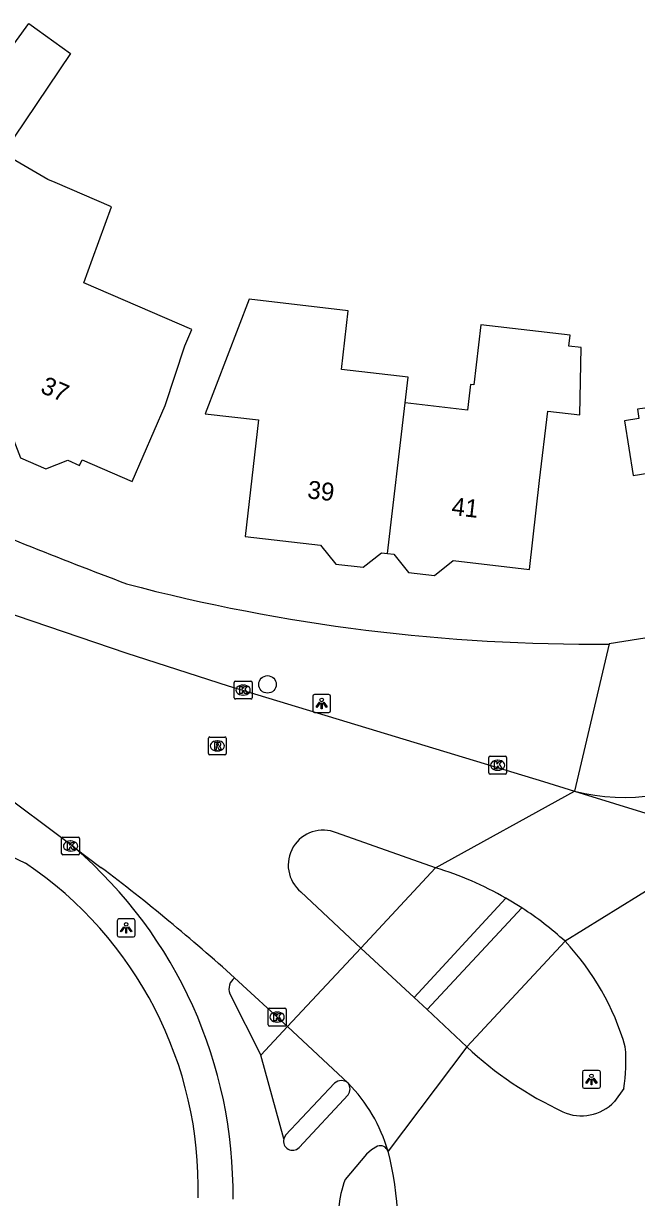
# Model space of a CAD drawing. Extents: x 161354 to 161876, y 382161 to 382804.
# Drawn here: x 161714.8 to 161749.1, y 382269.2 to 382334.8 of the extents above; entities that cross this region are included whole.
import ezdxf

# ---------------------------------------------------------------- set-up
doc = ezdxf.new("R2010")
doc.units = 0
for name, color, linetype in [('IMGEO_Boom', 7, 'Continuous'), ('IMGEO_Fietspad_open', 7, 'Continuous'), ('IMGEO_Kolk', 7, 'Continuous'), ('IMGEO_Lichtpunt', 7, 'Continuous'), ('IMGEO_Pand', 7, 'Continuous'), ('IMGEO_Pand_nummerreeks', 7, 'Continuous'), ('IMGEO_Rijbaan_lokaal_gesloten', 7, 'Continuous'), ('IMGEO_Rioolput', 7, 'Continuous'), ('IMGEO_Voetpad_open', 7, 'Continuous')]:
    doc.layers.add(name, color=color, linetype=linetype)

msp = doc.modelspace()

# ---------------------------------------------------------------- linework, layer by layer
at = {"layer": 'IMGEO_Boom'}
msp.add_circle((161728.459, 382297.901), 0.489, dxfattribs=at)
at = {"layer": 'IMGEO_Fietspad_open'}
for points in [[(161737.377, 382279.736), (161742.662, 382285.419)], [(161745.072, 382283.557), (161739.581, 382277.651)], [(161726.36, 382280.622), (161728.093, 382277.186)], [(161729.365, 382272.515), (161728.093, 382277.186)], [(161730.22, 382272.03), (161732.955, 382274.978)], [(161734.597, 382272.115), (161734.273, 382271.909), (161733.995, 382271.658), (161732.797, 382270.252)]]:
    msp.add_lwpolyline(points, dxfattribs=at)
for centre, radius, start, end in [((161748.345, 382302.186), 10.599, 255.02337, 304.34641), ((161701.047, 382269.471), 25.49, 359.29627, 49.21338), ((161727.073, 382280.895), 0.764, 126.1329, 200.94169), ((161732.549, 382275.308), 0.523, 320.92712, 38.72404), ((161729.859, 382272.391), 0.51, 165.87454, 314.99719), ((161734.749, 382271.668), 0.472, 20.70473, 108.81872), ((161738.631, 382268.069), 6.229, 159.4877, 189.85638)]:
    msp.add_arc(centre, radius, start, end, dxfattribs=at)
at = {"layer": 'IMGEO_Kolk'}
for p, q in [((161726.599, 382297.161), (161726.599, 382298.013)), ((161726.674, 382298.087), (161727.526, 382298.087)), ((161727.6, 382298.013), (161727.6, 382297.161)), ((161727.11, 382297.307), (161727.085, 382297.307)), ((161727.087, 382297.867), (161727.112, 382297.867)), ((161727.526, 382297.087), (161726.674, 382297.087)), ((161740.81, 382292.963), (161740.81, 382293.815)), ((161740.885, 382293.889), (161741.737, 382293.889)), ((161741.298, 382293.669), (161741.323, 382293.669)), ((161741.811, 382293.815), (161741.811, 382292.963)), ((161741.737, 382292.889), (161740.885, 382292.889)), ((161741.321, 382293.109), (161741.296, 382293.109)), ((161716.965, 382288.451), (161716.965, 382289.303)), ((161717.04, 382289.377), (161717.892, 382289.377)), ((161717.453, 382289.157), (161717.478, 382289.157)), ((161717.966, 382289.303), (161717.966, 382288.451)), ((161717.892, 382288.377), (161717.04, 382288.377)), ((161717.476, 382288.597), (161717.451, 382288.597)), ((161728.496, 382278.895), (161728.496, 382279.747)), ((161728.571, 382279.821), (161729.423, 382279.821)), ((161728.984, 382279.601), (161729.009, 382279.601)), ((161729.497, 382279.747), (161729.497, 382278.895)), ((161729.007, 382279.041), (161728.982, 382279.041)), ((161729.423, 382278.821), (161728.571, 382278.821))]:
    msp.add_line(p, q, dxfattribs=at)
for points in [[(161726.599, 382297.161), (161726.599, 382298.013)], [(161726.674, 382298.087), (161727.526, 382298.087)], [(161727.6, 382298.013), (161727.6, 382297.161)], [(161726.92, 382297.787), (161727.043, 382297.787), (161727.043, 382297.636), (161727.173, 382297.787), (161727.337, 382297.787), (161727.191, 382297.636), (161727.344, 382297.387), (161727.192, 382297.387), (161727.107, 382297.551), (161727.043, 382297.484), (161727.043, 382297.387), (161726.92, 382297.387), (161726.92, 382297.787)], [(161727.526, 382297.087), (161726.674, 382297.087)], [(161740.81, 382292.963), (161740.81, 382293.815)], [(161740.885, 382293.889), (161741.737, 382293.889)], [(161741.131, 382293.589), (161741.254, 382293.589), (161741.254, 382293.438), (161741.384, 382293.589), (161741.548, 382293.589), (161741.402, 382293.438), (161741.555, 382293.189), (161741.403, 382293.189), (161741.318, 382293.353), (161741.254, 382293.286), (161741.254, 382293.189), (161741.131, 382293.189), (161741.131, 382293.589)], [(161741.811, 382293.815), (161741.811, 382292.963)], [(161741.737, 382292.889), (161740.885, 382292.889)], [(161716.965, 382288.451), (161716.965, 382289.303)], [(161717.04, 382289.377), (161717.892, 382289.377)], [(161717.286, 382289.077), (161717.409, 382289.077), (161717.409, 382288.926), (161717.539, 382289.077), (161717.703, 382289.077), (161717.557, 382288.926), (161717.71, 382288.677), (161717.558, 382288.677), (161717.473, 382288.841), (161717.409, 382288.774), (161717.409, 382288.677), (161717.286, 382288.677), (161717.286, 382289.077)], [(161717.966, 382289.303), (161717.966, 382288.451)], [(161717.892, 382288.377), (161717.04, 382288.377)], [(161728.496, 382278.895), (161728.496, 382279.747)], [(161728.571, 382279.821), (161729.423, 382279.821)], [(161729.497, 382279.747), (161729.497, 382278.895)], [(161728.817, 382279.521), (161728.94, 382279.521), (161728.94, 382279.37), (161729.07, 382279.521), (161729.234, 382279.521), (161729.088, 382279.37), (161729.241, 382279.121), (161729.089, 382279.121), (161729.004, 382279.285), (161728.94, 382279.218), (161728.94, 382279.121), (161728.817, 382279.121), (161728.817, 382279.521)], [(161729.423, 382278.821), (161728.571, 382278.821)]]:
    msp.add_lwpolyline(points, dxfattribs=at)
for centre, start, end in [((161726.676, 382298.011), 91.55205, 178.44795), ((161726.676, 382298.011), 91.55205, 178.44795), ((161727.524, 382298.011), 1.55205, 88.44795), ((161727.524, 382298.011), 1.55205, 88.44795), ((161726.676, 382297.163), 181.55205, 268.44795), ((161726.676, 382297.163), 181.55205, 268.44795), ((161727.524, 382297.163), 271.55205, 358.44795), ((161727.524, 382297.163), 271.55205, 358.44795), ((161740.887, 382293.813), 91.55205, 178.44795), ((161740.887, 382293.813), 91.55205, 178.44795), ((161741.735, 382293.813), 1.55205, 88.44795), ((161741.735, 382293.813), 1.55205, 88.44795), ((161740.887, 382292.965), 181.55205, 268.44795), ((161740.887, 382292.965), 181.55205, 268.44795), ((161741.735, 382292.965), 271.55205, 358.44795), ((161741.735, 382292.965), 271.55205, 358.44795), ((161717.042, 382289.301), 91.55205, 178.44795), ((161717.042, 382289.301), 91.55205, 178.44795), ((161717.89, 382289.301), 1.55205, 88.44795), ((161717.89, 382289.301), 1.55205, 88.44795), ((161717.042, 382288.453), 181.55205, 268.44795), ((161717.042, 382288.453), 181.55205, 268.44795), ((161717.89, 382288.453), 271.55205, 358.44795), ((161717.89, 382288.453), 271.55205, 358.44795), ((161728.573, 382279.745), 91.55205, 178.44795), ((161728.573, 382279.745), 91.55205, 178.44795), ((161729.421, 382279.745), 1.55205, 88.44795), ((161729.421, 382279.745), 1.55205, 88.44795), ((161728.573, 382278.897), 181.55205, 268.44795), ((161728.573, 382278.897), 181.55205, 268.44795), ((161729.421, 382278.897), 271.55205, 358.44795), ((161729.421, 382278.897), 271.55205, 358.44795)]:
    msp.add_arc(centre, 0.0765, start, end, dxfattribs=at)
for centre, major_axis, ratio, start_param, end_param in [((161727.086, 382297.587), (-0.387, 0.002), 0.722429, 4.712389, 7.853982), ((161727.111, 382297.587), (-0.39, 0.002), 0.717154, 1.570796, 4.712389), ((161741.297, 382293.389), (-0.387, 0.002), 0.722429, 4.712389, 7.853982), ((161741.322, 382293.389), (-0.39, 0.002), 0.717154, 1.570796, 4.712389), ((161717.452, 382288.877), (-0.387, 0.002), 0.722429, 4.712389, 7.853982), ((161717.477, 382288.877), (-0.39, 0.002), 0.717154, 1.570796, 4.712389), ((161728.983, 382279.321), (-0.387, 0.002), 0.722429, 4.712389, 7.853982), ((161729.008, 382279.321), (-0.39, 0.002), 0.717154, 1.570796, 4.712389)]:
    msp.add_ellipse(centre, major_axis=major_axis, ratio=ratio, start_param=start_param, end_param=end_param, dxfattribs=at)
at = {"layer": 'IMGEO_Lichtpunt'}
for p, q in [((161731.888, 382297.334), (161731.08, 382297.334)), ((161731.888, 382297.334), (161731.08, 382297.334)), ((161730.986, 382297.239), (161730.986, 382296.432)), ((161730.986, 382297.239), (161730.986, 382296.432)), ((161731.982, 382296.432), (161731.982, 382297.239)), ((161731.982, 382296.432), (161731.982, 382297.239)), ((161731.08, 382296.338), (161731.888, 382296.338)), ((161731.08, 382296.338), (161731.888, 382296.338)), ((161720.068, 382284.705), (161720.068, 382283.898)), ((161720.068, 382284.705), (161720.068, 382283.898)), ((161720.97, 382284.8), (161720.162, 382284.8)), ((161720.97, 382284.8), (161720.162, 382284.8)), ((161721.064, 382283.898), (161721.064, 382284.705)), ((161721.064, 382283.898), (161721.064, 382284.705)), ((161720.162, 382283.804), (161720.97, 382283.804)), ((161720.162, 382283.804), (161720.97, 382283.804)), ((161746.947, 382276.34), (161746.139, 382276.34)), ((161746.947, 382276.34), (161746.139, 382276.34)), ((161746.045, 382276.245), (161746.045, 382275.438)), ((161746.045, 382276.245), (161746.045, 382275.438)), ((161747.041, 382275.438), (161747.041, 382276.245)), ((161747.041, 382275.438), (161747.041, 382276.245)), ((161746.139, 382275.344), (161746.947, 382275.344)), ((161746.139, 382275.344), (161746.947, 382275.344))]:
    msp.add_line(p, q, dxfattribs=at)
for points in [[(161731.36, 382296.903), (161731.399, 382296.875), (161731.211, 382296.613), (161731.173, 382296.64), (161731.36, 382296.903)], [(161731.462, 382296.855), (161731.509, 382296.855), (161731.509, 382296.533), (161731.462, 382296.533), (161731.462, 382296.855)], [(161731.572, 382296.875), (161731.61, 382296.902), (161731.797, 382296.64), (161731.758, 382296.612), (161731.572, 382296.875)], [(161720.442, 382284.369), (161720.481, 382284.341), (161720.293, 382284.079), (161720.255, 382284.106), (161720.442, 382284.369)], [(161720.544, 382284.321), (161720.591, 382284.321), (161720.591, 382283.999), (161720.544, 382283.999), (161720.544, 382284.321)], [(161720.654, 382284.341), (161720.692, 382284.368), (161720.879, 382284.106), (161720.84, 382284.078), (161720.654, 382284.341)], [(161746.419, 382275.909), (161746.458, 382275.881), (161746.27, 382275.619), (161746.232, 382275.646), (161746.419, 382275.909)], [(161746.521, 382275.861), (161746.568, 382275.861), (161746.568, 382275.539), (161746.521, 382275.539), (161746.521, 382275.861)], [(161746.631, 382275.881), (161746.669, 382275.908), (161746.856, 382275.646), (161746.817, 382275.618), (161746.631, 382275.881)]]:
    msp.add_lwpolyline(points, dxfattribs=at)
for centre in [(161731.485, 382297.037), (161720.567, 382284.503), (161746.544, 382276.043)]:
    msp.add_circle(centre, 0.0994, dxfattribs=at)
for centre, start, end in [((161731.08, 382297.239), 90, 180), ((161731.08, 382297.239), 90, 180), ((161731.888, 382297.239), 0, 90), ((161731.888, 382297.239), 0, 90), ((161731.08, 382296.432), 180, 270), ((161731.08, 382296.432), 180, 270), ((161731.888, 382296.432), 270, 0), ((161731.888, 382296.432), 270, 360), ((161720.162, 382284.705), 90, 180), ((161720.162, 382284.705), 90, 180), ((161720.97, 382284.705), 0, 90), ((161720.97, 382284.705), 0, 90), ((161720.162, 382283.898), 180, 270), ((161720.162, 382283.898), 180, 270), ((161720.97, 382283.898), 270, 0), ((161720.97, 382283.898), 270, 360), ((161746.139, 382276.245), 90, 180), ((161746.139, 382276.245), 90, 180), ((161746.947, 382276.245), 0, 90), ((161746.947, 382276.245), 0, 90), ((161746.139, 382275.438), 180, 270), ((161746.139, 382275.438), 180, 270), ((161746.947, 382275.438), 270, 0), ((161746.947, 382275.438), 270, 360)]:
    msp.add_arc(centre, 0.0946, start, end, dxfattribs=at)
at = {"layer": 'IMGEO_Pand'}
for points in [[(161707.794, 382333.736), (161712.072, 382330.605), (161715.133, 382334.815), (161717.458, 382333.145), (161713.667, 382327.503), (161713.965, 382327.4)], [(161711.832, 382324.112), (161711.351, 382323.387), (161713.706, 382322.37), (161710.058, 382313.92), (161713.718, 382312.34), (161713.582, 382312.025), (161714.196, 382311.76), (161714.676, 382310.552), (161716.09, 382309.942), (161717.306, 382310.425), (161717.973, 382310.137), (161718.11, 382310.453), (161720.912, 382309.243), (161722.74, 382313.478), (161723.843, 382316.818), (161724.233, 382317.722), (161718.202, 382320.324), (161718.445, 382320.992), (161718.691, 382321.669), (161719.748, 382324.574), (161716.614, 382325.927), (161716.201, 382326.105), (161713.965, 382327.4)], [(161736.14, 382313.623), (161736.307, 382315.063), (161732.592, 382315.493), (161732.972, 382318.772), (161727.429, 382319.414), (161724.978, 382313.01), (161727.958, 382312.67), (161727.215, 382306.162), (161731.424, 382305.681), (161732.269, 382304.617), (161733.801, 382304.442), (161734.826, 382305.257), (161735.168, 382305.218)], [(161735.168, 382305.218), (161735.509, 382305.179), (161736.323, 382304.155), (161737.776, 382303.988), (161738.816, 382304.815), (161743.086, 382304.326), (161743.654, 382309.294), (161744.108, 382313.167), (161745.896, 382312.958), (161745.98, 382316.718), (161745.28, 382316.798), (161745.349, 382317.404), (161740.367, 382317.976), (161739.984, 382314.638), (161739.795, 382314.66), (161739.722, 382314.021), (161739.63, 382313.219), (161736.14, 382313.623)], [(161748.395, 382312.614), (161748.865, 382309.565), (161749.686, 382309.692), (161750.425, 382304.894), (161755.015, 382305.601), (161754.956, 382305.987), (161758.404, 382306.518), (161758.037, 382308.906), (161758.735, 382309.013), (161757.975, 382313.955), (161757.874, 382314.613), (161753.737, 382313.977), (161753.388, 382316.245), (161749.721, 382315.681), (161750.071, 382313.413), (161749.109, 382313.265), (161749.188, 382312.754), (161748.395, 382312.614)], [(161735.168, 382305.218), (161736.14, 382313.623)]]:
    msp.add_lwpolyline(points, dxfattribs=at)
at = {"layer": 'IMGEO_Rijbaan_lokaal_gesloten'}
for points in [[(161705.294, 382305.538), (161705.79, 382305.306), (161706.287, 382305.077), (161712.666, 382302.344), (161720.606, 382299.646), (161721.129, 382299.474), (161726.271, 382297.814), (161743.873, 382292.487), (161745.606, 382291.947)], [(161717.698, 382288.771), (161713.02, 382292.272), (161710.614, 382293.536), (161705.719, 382296.186), (161701.507, 382298.575), (161695.116, 382302.112), (161692.781, 382303.491), (161692.274, 382303.804), (161691.768, 382304.12)], [(161737.842, 382287.653), (161745.606, 382291.947)], [(161745.606, 382291.947), (161754.287, 382289.266)], [(161737.842, 382287.653), (161732.318, 382289.613)], [(161717.698, 382288.771), (161719.156, 382287.682)], [(161754.287, 382289.266), (161745.072, 382283.557)], [(161730.323, 382286.31), (161733.677, 382283.171)], [(161742.662, 382285.419), (161741.759, 382285.97)], [(161729.577, 382278.798), (161733.677, 382283.171)], [(161736.653, 382280.408), (161733.677, 382283.171)], [(161729.577, 382278.798), (161726.623, 382281.512)], [(161736.653, 382280.408), (161737.377, 382279.736)], [(161739.581, 382277.651), (161737.377, 382279.736)], [(161729.577, 382278.798), (161732.957, 382275.635)], [(161739.581, 382277.651), (161735.191, 382271.835)], [(161748.358, 382275.329), (161747.828, 382274.606)]]:
    msp.add_lwpolyline(points, dxfattribs=at)
for centre, radius, start, end in [((161731.566, 382287.814), 1.95, 67.30752, 230.42884), ((161654.402, 382201.713), 107.628, 47.85387, 53.01212), ((161732.424, 382269.644), 18.807, 60.24028, 73.25666), ((161732.454, 382269.717), 18.728, 47.64613, 56.97351), ((161734.599, 382273.682), 14.395, 16.01511, 43.31777), ((161754.115, 382293.411), 21.438, 227.31706, 244.67909), ((161738.988, 382276.803), 9.485, 351.06139, 5.14329), ((161726.547, 382269.31), 9.005, 16.28343, 44.61866), ((161745.986, 382276.33), 2.523, 245.6421, 316.88599), ((161717.131, 382267.293), 18.622, 350.70557, 14.11808)]:
    msp.add_arc(centre, radius, start, end, dxfattribs=at)
at = {"layer": 'IMGEO_Rioolput'}
for p, q in [((161725.159, 382294.038), (161725.159, 382294.89)), ((161725.234, 382294.964), (161726.086, 382294.964)), ((161725.647, 382294.744), (161725.672, 382294.744)), ((161726.16, 382294.89), (161726.16, 382294.038)), ((161725.67, 382294.184), (161725.645, 382294.184)), ((161726.086, 382293.964), (161725.234, 382293.964))]:
    msp.add_line(p, q, dxfattribs=at)
for points in [[(161725.159, 382294.038), (161725.159, 382294.89)], [(161725.234, 382294.964), (161726.086, 382294.964)], [(161726.16, 382294.89), (161726.16, 382294.038)], [(161725.748, 382294.662), (161725.496, 382294.664), (161725.496, 382294.264)], [(161725.496, 382294.264), (161725.62, 382294.264), (161725.62, 382294.426), (161725.631, 382294.426)], [(161725.674, 382294.583), (161725.62, 382294.583), (161725.62, 382294.502)], [(161725.62, 382294.502), (161725.672, 382294.502)], [(161725.678, 382294.397), (161725.749, 382294.264), (161725.889, 382294.264), (161725.824, 382294.39)], [(161726.086, 382293.964), (161725.234, 382293.964)]]:
    msp.add_lwpolyline(points, dxfattribs=at)
for centre, radius, start, end in [((161725.236, 382294.888), 0.0765, 91.55205, 178.44795), ((161725.236, 382294.888), 0.0765, 91.55205, 178.44795), ((161726.084, 382294.888), 0.0765, 1.55205, 88.44795), ((161726.084, 382294.888), 0.0765, 1.55205, 88.44795), ((161725.236, 382294.04), 0.0765, 181.55205, 268.44795), ((161725.236, 382294.04), 0.0765, 181.55205, 268.44795), ((161725.63, 382294.373), 0.0533, 26.02933, 88.69889), ((161725.656, 382294.691), 0.19, 274.7715, 282.96867), ((161725.68, 382294.487), 0.0964, 77.00612, 93.18647), ((161725.694, 382294.544), 0.0378, 276.66336, 79.67722), ((161725.747, 382294.552), 0.109, 350.36119, 89.41601), ((161725.745, 382294.552), 0.112, 277.58423, 350.98172), ((161725.729, 382294.337), 0.108, 29.51342, 73.79051), ((161726.084, 382294.04), 0.0765, 271.55205, 358.44795), ((161726.084, 382294.04), 0.0765, 271.55205, 358.44795)]:
    msp.add_arc(centre, radius, start, end, dxfattribs=at)
for centre, major_axis, ratio, start_param, end_param in [((161725.646, 382294.464), (-0.387, 0.002), 0.722429, 4.712389, 7.853982), ((161725.671, 382294.464), (-0.39, 0.002), 0.717154, 1.570796, 4.712389)]:
    msp.add_ellipse(centre, major_axis=major_axis, ratio=ratio, start_param=start_param, end_param=end_param, dxfattribs=at)
at = {"layer": 'IMGEO_Voetpad_open'}
for points in [[(161677.151, 382309.804), (161686.732, 382302.424), (161697.545, 382295.944), (161703.155, 382293.259), (161711.315, 382289.649), (161714.958, 382287.913)], [(161786.77, 382309.433), (161785.539, 382308.875), (161785.615, 382308.486), (161774.681, 382305.586), (161768.027, 382303.924), (161762.045, 382302.471), (161747.542, 382300.159)], [(161747.542, 382300.159), (161745.606, 382291.947)], [(161733.677, 382283.171), (161737.842, 382287.653)], [(161741.759, 382285.97), (161736.653, 382280.408)], [(161728.093, 382277.186), (161729.577, 382278.798)], [(161732.207, 382275.626), (161729.469, 382272.718), (161729.365, 382272.515)]]:
    msp.add_lwpolyline(points, dxfattribs=at)
for centre, radius, start, end in [((161823.77, 382576.859), 292.166, 246.94072, 249.31777), ((161746.507, 382401.615), 101.462, 255.19529, 270.58449), ((161702.722, 382269.783), 21.873, 358.52376, 55.98572), ((161732.587, 382275.228), 0.55, 47.74404, 133.631)]:
    msp.add_arc(centre, radius, start, end, dxfattribs=at)

# ---------------------------------------------------------------- texts
at = {"layer": 'IMGEO_Pand_nummerreeks'}
for s, rotation, p in [('37', 336.68635, (161715.724, 382314.224)), ('39', 353.4012, (161730.651, 382308.302)), ('41', 353.4012, (161738.7, 382307.371))]:
    msp.add_text(s, height=1, rotation=rotation, dxfattribs=at).set_placement(p)

doc.saveas('drawing.dxf')
